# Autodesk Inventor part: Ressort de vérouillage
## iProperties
Author: Flavien MARTY
Shininess: 27.0
PropertySet Name: _Private Model Information
Created: 2001-10
Part Number: Ressort de vérouillage
Material: Par défaut
Document SubType Name: Modélisation
Designer: Flavien MARTY
Control State: 0
Master: False
Checked Out: False
PropertySet Name: Design Tracking Control
Density: 0.0
Volumn: 0.0
Area: 0.0
PropertySet Name: Model Information
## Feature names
1. Base1
